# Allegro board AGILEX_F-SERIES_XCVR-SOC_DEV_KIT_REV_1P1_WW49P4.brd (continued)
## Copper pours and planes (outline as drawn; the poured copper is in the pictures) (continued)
VCCL_HPS_FPGA_0.9V on ART20: 107.29,109.6 107.29,106.17 107.27,106.16 107.27,104.28 105.32,102.33 105.32,91.19 101.68,87.54 101.68,84.66 101.69,84.65 101.69,79.84 105.69,75.84 105.69,51.03 104.34,49.68 78.84,49.68 69.42,40.26 55.2,40.26 48.26,47.19 46.15,47.19 38.51,39.55 18.87,39.55 15.53,42.89 15.53,98.87 31.47,114.81 57.68,114.81 64.54,107.95 86.11,107.95 88.34,110.19 91.8,110.19 94.11,112.5 100.51,112.5 103.15,109.85 107.03,109.85
VCCL_SDM_FPGA_0.8V on BOTTOM: 123.57,76.4 123.62,76.35 129.54,76.35 129.61,76.43 129.61,78.33 128.83,79.12 124.21,79.12 123.57,78.48
VCCL_SDM_FPGA_0.8V on BOTTOM: 129.59,27.13 129.29,27.43 129.29,29.82 129.44,29.97 131.75,29.97 131.98,29.74 131.98,27.3 131.8,27.13
VCCL_SDM_FPGA_0.8V on POWER09: 125.96,27.38 125.96,59.41 114.02,71.35 114.02,93.37 114.12,93.47 116.28,93.47 116.69,93.87 116.69,95.27 116.79,95.38 120.52,95.38 120.62,95.27 120.62,81.3 122.8,79.12 126.49,79.12 130.55,75.06 134.47,75.06 134.47,73.55 141.7,66.31 141.7,27.74 140.74,26.77 126.57,26.77
VCCLPLLDIG_HPS_FPGA_0.9V on BOTTOM: 68.17,98.17 68.17,100.84 68.43,101.09 70.33,101.09 70.58,100.84 70.58,98.42 70.33,98.17
VCCLPLLDIG_HPS_FPGA_0.9V on ART03: 104.87,112.01 105.38,111.51 105.38,109.73 93.85,98.2 68.43,98.2 68.06,98.56 68.06,107.35 69.93,109.22 95,109.22 97.79,112.01
VCCLPLLDIG_SDM_FPGA_0.8V on BOTTOM: 130.3,79.04 133.3,79.04 133.5,78.84 133.5,76.48 133.22,76.2 130.32,76.2 130.02,76.5 130.02,78.76
VCCLPLLDIG_SDM_FPGA_0.8V on POWER09: 130.76,75.56 126.7,79.63 123.01,79.63 121.13,81.51 121.13,93.49 121.15,93.47 123.9,93.47 124.05,93.62 124.05,92.1 124.71,91.44 132.84,91.44 134.47,89.81 134.47,75.56
VCCPT_FLTR_FPGA_1.8V on BOTTOM: 154.36,78.54 154.36,76.94 153.59,76.17 153.59,70.64 158.95,65.28 160.05,65.28 162.1,67.34 162.1,80.06 161.85,80.31 159.87,80.31 158.83,79.27 155.09,79.27
VCCPT_FLTR_FPGA_1.8V on ART16: 107.82,115.06 113.41,109.47 115.57,109.47 117.09,107.95 117.09,95.63 119.38,93.34 126.11,93.34 127,92.46 127,91.82 126.24,91.06 122.94,91.06 121.67,89.79 121.67,81.92 124.71,78.87 129.92,78.87 131.32,77.47 131.32,75.18 140.02,66.48 145.1,66.48 146.3,65.28 150.75,65.28 155.19,69.72 159.38,69.72 160.27,68.83 160.27,66.29 157.73,63.75 138.56,63.75 130.56,71.75 123.44,71.75 113.67,81.53 113.67,88.77 112.39,90.04 112.39,91.69 106.36,97.73 106.36,105.6 100.97,111 100.97,114.68 101.35,115.06
VCCPT_FPGA_1.8V on TOP (solid shape): outline of 209 points within 205.79,119.1 216.71,130.05
VCCPT_FPGA_1.8V on TOP (solid shape): outline of 305 points within 187.68,118.64 199.49,130.1
VCCPT_FPGA_1.8V on BOTTOM: 208.45,122.95 207.11,124.28 207.11,126.92 206.32,127.71 202.21,127.71 201.9,127.41 199.97,127.41 199.49,126.92 199.49,124.54 199.11,124.16 198.32,124.16 198.07,123.9 198.07,119.76 197.66,119.35 193.5,119.35 192.25,120.6 192.25,121.69 192.28,121.72 191.9,122.1 189.99,122.1 189.71,121.82 189.71,121.41 189.36,121.77 187.58,121.77 187.27,121.46 187.27,117.63 187.5,117.4 188.19,117.4 188.94,116.65 188.94,112.1 188.57,111.73 161.77,111.73 161.76,111.75 160.26,111.75 157.33,114.68 154.4,114.68 151.86,112.14 144.75,112.14 144.5,112.39 144.5,115.01 144.55,115.06 150.42,115.06 153.38,118.02 157.14,118.02 157.61,118.49 157.61,125.09 156.72,125.98 156.72,127.38 156.34,127.76 156.34,129.41 162.18,129.41 162.51,129.08 192.35,129.08 192.89,128.55 194.56,128.55 196.16,130.15 216.15,130.15 216.89,129.41 216.89,119.51 216.56,119.18 214.58,119.18 214.12,118.72 209.32,118.72 208.45,119.6
VCCPT_FPGA_1.8V on BOTTOM: 155.83,92.53 155.83,93.32 156.1,93.59 157.53,93.59 158.56,94.61 161.37,94.61 162.38,93.6 162.38,89.66 161.47,88.75 161.47,85.67 162.31,84.84 162.31,81.41 161.9,81 159.33,81 158.22,79.88 153.67,79.88 151.13,82.42 151.13,90.14 152.43,91.44 154.74,91.44
VCCPT_FPGA_1.8V on GND13: 215.49,142.62 215.49,116.26 215.01,115.77 193.07,115.77 191.87,116.97 191.87,140.87 194.56,143.56 214.55,143.56
VCCPT_FPGA_1.8V on POWER14: 115.54,108.71 110.24,108.71 109.73,108.2 109.73,95 110.24,94.49 115.42,94.49 115.92,95 115.92,95 116.18,95.25 118.72,95.25 119.48,94.49 122.94,94.49 123.44,93.98 123.44,79.25 124.46,78.23 158.72,78.23 159.55,79.06 159.55,94.71 158.85,95.4 158.85,102.95 159.54,103.63 187.45,103.63 200.15,116.33 200.15,121.51 200.1,121.56 200.1,122.07 200.15,122.12 200.15,145.8 199.64,146.3 182.88,146.3 182.8,146.23 154.35,146.23 153.67,145.54 153.67,138.3 152.32,136.96 128.32,136.96 119.89,128.52 119.89,109.22 118.87,108.2 118.84,108.2 118.72,108.08 116.18,108.08
VCCRT_GXE_FPGA_0.9V on BOTTOM: 81.13,89.03 81.13,102.54 80.95,102.72 80.7,102.72 80.67,102.74 79.04,102.74 76.73,105.05 74.01,105.05 71.12,107.95 70.46,107.95 69.82,108.58 69.82,112.24 70.28,112.7 90.7,112.7 92.25,111.15 92.25,89.86 91.41,89.03
VCCRT_GXE_FPGA_0.9V on POWER14: 100.11,106.11 100.18,106.04 103.6,106.04 104.24,105.41 104.24,78.61 103.86,78.23 81.51,78.23 80.49,79.25 80.49,95.45 72.42,103.53 72.42,108.53 73.86,109.98 99.67,109.98 100.11,109.54
VCCRT_GXE_FPGA_0.9V on ART16: 81.25,89.41 81.25,91.73 78.32,94.67 78.32,105.61 78.77,106.06 97.19,106.06 97.91,105.34 97.91,101.16 97.38,100.63 97.38,98.32 97.47,98.23 97.49,98.23 97.91,97.82 97.91,94.32 92.61,89.01 81.65,89.01
VCCRT_GXP_FPGA_0.9V on BOTTOM: 141.32,113.54 139.42,113.54 138.91,113.03 138.91,105.69 139.32,105.28 141.81,105.28 141.83,105.31 141.83,113.03
VCCRT_GXP_FPGA_0.9V on POWER09: 134.82,90.17 133.05,91.95 124.92,91.95 124.56,92.31 124.56,109.49 124.92,109.85 147.29,109.85 147.29,90.66 146.81,90.17
VCCRTPLL_GXE_FPGA_0.9V on BOTTOM: 77.37,94.26 75.77,94.26 75.44,93.93 75.44,85.37 75.66,85.14 77.24,85.14 77.77,85.67 77.77,93.85
VCCRTPLL_GXE_FPGA_0.9V on ART16: 77.04,82.02 75.79,83.26 75.79,91.77 76.05,92.02 80.24,92.02 81.78,90.49 84.44,90.49 85.98,92.02 89.84,92.02 97.73,99.92 97.73,100.69 98.2,101.16 98.2,102.87 98.84,103.52 103.35,103.52 104.29,102.58 104.29,92.82 103.12,91.66 102.06,91.66 98.3,87.9 98.3,82.51 97.8,82.02
VDD_SODIMM on TOP (solid shape): 80.37,50.34 80.37,49.23 80.8,48.79 80.8,48.03 80.57,47.8 80.57,42.75 79.98,42.16 78.08,42.16 77.85,42.39 77.85,47.37 79.35,48.87 79.4,48.87 79.58,49.05 79.58,49.53 79.67,49.62 79.71,49.75 79.71,50 79.63,50.18 79.45,50.26 79.21,50.26 79.14,50.28 79.07,50.28 79,50.28 78.93,50.26 78.8,50.26 78.8,50.5 80.21,50.5
VDD_SODIMM on TOP: 114,29.72 114,24.82 114.48,24.33 117.3,24.33 118.03,25.07 118.03,29.67 117.63,30.07 114.35,30.07
VDD_SODIMM on BOTTOM: 114.25,29.77 114.25,26.29 114.76,25.78 117.65,25.78 117.88,26.01 117.88,29.64 117.6,29.92 114.4,29.92
VDD_SODIMM on POWER11: 181.96,76.33 181.96,3.05 98.81,3.05 98.42,3.43 98.42,76.83 181.46,76.83
VDD_SODIMM on ART16: 67.79,57.53 118.21,57.53 124.81,50.93 124.81,42.04 123.04,40.26 68.3,40.26 67.03,41.53 67.03,56.77
(no net) on TOP: 202.46,181.64 201.93,182.17 201.93,186.44 202.18,186.69 203.86,186.69 204.32,186.23 204.32,184.35 205.54,183.13 210.74,183.13 210.78,183.17 215.79,183.17 215.81,183.2 216.4,183.2 216.41,183.19 217.17,183.19 217.37,182.98 217.37,181.89 217.12,181.64
(no net) on TOP: 200.1,208.89 194.11,208.89 193.73,208.51 193.73,206.04 194.18,205.59 200.28,205.59 200.53,205.84 200.53,208.46
(no net) on TOP: 199.21,130.1 199.49,129.82 199.49,124.54 198.36,123.41 198.36,122.59 198.88,122.07 198.88,118.77 198.75,118.64 194.89,118.64 193.19,120.35 193.19,123.14 192.38,123.95 188.39,123.95 187.68,124.66 187.68,128.17 187.91,128.4 192.86,128.4 194.56,130.1
(no net) on TOP: 202.53,193.31 202.23,193.6 202.23,195.15 201.4,195.99 197.66,195.99 197.36,196.29 197.36,197 196.8,197.56 189.66,197.56 189.26,197.97 189.26,200.08 189.87,200.69 199.21,200.69 199.67,201.14 199.67,201.52 199.86,201.71 201.74,201.71 201.88,201.57 201.88,198.37 202.29,197.97 207.24,197.97 207.52,198.25 207.52,202.95 208.38,203.81 208.38,208.56 208,208.94 208,211.51 208.13,211.63 209.65,211.63 211.18,210.11 214.93,210.11 216.69,208.36 216.69,195.53 216.48,195.33 214.99,195.33 214.35,195.96 206.48,195.96 205.89,195.38 205.89,193.6 205.6,193.31
(no net) on TOP: 203.45,192.56 203.45,190.88 203.84,190.5 206.55,190.5 206.98,190.07 206.98,188.9 207.54,188.34 209.37,188.34 209.68,188.65 209.68,190.45 209.02,191.11 208.74,191.11 208.74,191.54 207.8,192.48 207.19,192.48 206.78,192.89 203.78,192.89
(no net) on TOP: 207.19,195.35 207.19,193.32 207.57,192.94 207.9,192.94 209.07,191.77 209.35,191.77 209.8,191.31 209.8,188.26 210.16,187.91 210.16,186.03 211.66,184.53 216.15,184.53 216.6,184.98 216.6,194.32 215.99,194.93 214.88,194.93 214.26,195.55 207.39,195.55
(no net) on TOP: 202.06,127.05 202.06,125.37 202.44,124.99 205.16,124.99 205.59,124.56 205.59,123.72 205.74,123.57 207.77,123.57 207.77,123.75 208.28,124.26 208.28,125.98 207.75,126.52 206.58,126.52 205.69,127.41 205.38,127.41 205.38,127.38 202.39,127.38
(no net) on TOP: 201.13,127.8 200.84,128.09 200.84,129.64 200,130.48 194.23,130.48 193.78,130.02 186.54,130.02 186.26,130.3 186.26,132.08 186.82,132.64 193.47,132.64 193.8,132.97 193.8,134.29 194.69,135.18 197.82,135.18 198.27,135.64 198.27,136.02 198.46,136.21 200.34,136.21 200.48,136.07 200.48,132.87 200.89,132.46 205.84,132.46 206.12,132.74 206.12,140.18 207.16,141.22 207.16,148.74 207.26,148.84 211.81,148.84 211.84,148.87 216.26,148.87 217.37,147.75 217.37,131.17 216.61,130.4 213.36,130.4 212.75,131.01 211.28,131.01 210.72,130.45 205.08,130.45 204.5,129.87 204.5,128.09 204.2,127.8
(no net) on TOP: 202.06,185.9 202.11,185.95 203.76,185.95 204.11,185.6 204.11,184.28 203.84,184 202.18,184 202.06,184.12
(no net) on TOP: 85.09,50.77 79.04,50.77 78.84,50.98 78.84,51.16 78.89,51.21 79.98,51.21 80.54,51.77 80.54,53.04 81.23,53.72 88.54,53.72 89.15,53.11 89.15,52.45 90.3,51.31 91.19,51.31 91.31,51.18 91.31,48.26 87.6,48.26
(no net) on TOP: 200.9,133.16 201.12,132.94 205.51,132.94 205.71,133.15 205.71,137.67 205.51,137.87 205.51,148.69 205.26,148.95 201.29,148.95 200.66,148.31 200.66,142.39 200.48,142.21 200.48,140.31 200.56,140.23 200.84,140.23 201.09,139.98 201.09,138.66 201.93,137.82 201.93,136.5 201.65,136.22 201.23,136.22 200.9,135.89
(no net) on TOP: 84.86,50.37 86.33,48.9 86.33,45.47 86.09,45.22 84.07,45.22 83.81,44.96 83.82,44.96 83.82,42.67 83.31,42.16 81.15,42.16 80.98,42.34 80.98,47.29 81.23,47.55 81.23,49.05 80.87,49.4 80.87,50.16 81.08,50.37
(no net) on TOP: 57.18,131.85 57.18,129.95 57.06,129.83 55.11,129.83 54.95,129.98 53.1,129.98 52.73,130.35 52.73,131.95 53.1,132.32 55.13,132.32 55.45,132 57.02,132
(no net) on TOP: 205.79,129.84 205.79,127.76 206.45,127.1 206.88,127.1 207.26,126.72 207.26,126.7 208.05,126.7 208.41,126.34 208.41,122.76 208.76,122.4 209.83,122.4 210.77,121.46 210.77,119.94 211.61,119.1 216.46,119.1 216.71,119.35 216.71,128.3 216.2,128.8 213.31,128.8 212.06,130.05 205.99,130.05
(no net) on TOP: 202.3,198.67 202.51,198.45 206.91,198.45 207.11,198.65 207.11,203.17 206.68,203.61 206.68,212.45 206.32,212.8 204.47,212.8 203.28,214 201.68,214 201.19,213.51 201.19,205.84 201.45,205.59 202.49,205.59 202.77,205.31 202.77,203.45 203.25,202.97 203.25,202.3 203.03,202.08 202.64,202.08 202.3,201.74
(no net) on TOP: 79.98,42.16 80.57,42.75 80.57,47.8 80.8,48.03 80.8,48.79 80.37,49.23 80.37,50.34 80.2,50.51 79.62,50.51 79.58,50.55 78.71,50.55 78.66,50.5 78.66,50.29 78.71,50.24 79.3,50.24 79.58,49.96 79.58,49.05 79.4,48.87 79.35,48.87 77.85,47.37 77.85,42.39 78.08,42.16
(no net) on TOP: 199.85,140.39 199.85,145.41 199.26,146 194.56,146 194.26,145.69 194.26,140.87 194.89,140.23 199.69,140.23
(no net) on TOP: 200.61,195.61 200.89,195.33 200.89,190.04 199.76,188.91 199.76,188.1 200.28,187.58 200.28,184.28 200.05,184.05 194.77,184.05 193.78,185.04 193.78,190.98 193.6,191.16 189.59,191.16 188.82,191.92 188.82,196.52 189.15,196.85 196.67,196.85 196.98,196.55 196.98,196.14 197.51,195.61
(no net) on BOTTOM: 4.79,181.34 5.36,181.91 8.98,181.91 9.49,181.4 9.49,177.97 7.84,176.32 7.84,170.99 8.86,169.97 11.52,169.97 12.22,169.27 12.22,162.23 11.91,161.92 5.18,161.92 4.79,162.31
(no net) on BOTTOM: 217.42,207.82 217.6,207.82 217.91,207.52 217.91,198.98 217.86,198.98 217.2,198.32 213.44,198.32 212.24,197.13 212.24,196.19 211.98,195.92 207.48,195.92 207.21,195.66 207.21,193.4 206.91,193.09 206.04,193.09 205.97,193.01 202.59,193.01 202.31,193.29 202.31,194.84 201.12,196.04 197.33,196.04 195.86,197.51 188.8,197.51 188.37,197.94 188.37,203.1 192.99,207.72 192.99,214.66 194.21,215.87 199.97,215.87 200.74,215.11 200.74,204.95 199.54,203.76 199.54,201.98 199.92,201.6 201.78,201.6 201.83,201.55 201.83,198.42 202.49,197.76 206.83,197.76 207.52,198.45 207.52,202.67 208.41,203.56 208.41,208.71 209.17,209.47 216.46,209.47 217.42,208.51
(no net) on BOTTOM: 198.35,136.83 198.68,136.5 200.41,136.5 200.91,135.99 200.91,133.15 201.14,132.92 205.51,132.92 205.97,133.38 205.97,148.26 205.44,148.79 201.47,148.79 201.27,148.59 201.27,139.85 200.43,139.01 199.06,139.01 198.35,138.3
(no net) on BOTTOM: 200.74,205.54 200.23,205.03 198.55,205.03 197.87,205.71 197.87,210.41 196.85,211.43 194.64,211.43 193.68,212.39 193.68,215.21 194.26,215.8 200.03,215.8 200.74,215.09
(no net) on BOTTOM: 13.33,169.84 12.75,169.27 12.75,166.14 12.79,166.1 12.79,162.44 13.18,162.05 15.85,162.05 16.36,162.56 16.36,169.27 15.78,169.84
(no net) on BOTTOM: 194.11,139.83 193.73,140.21 193.73,152.07 194.18,152.53 199.21,152.53 199.54,152.2 199.54,140.16 199.21,139.83
(no net) on BOTTOM: 202.35,203.82 201.93,203.4 200.18,203.4 199.75,202.97 199.75,202.21 199.92,202.03 201.75,202.03 202.16,201.63 202.16,198.58 202.41,198.32 207.09,198.32 207.26,198.5 207.26,203.2 207.37,203.3 207.37,212.27 207.06,212.57 205.59,212.57 204.04,214.12 202.31,214.12 202.18,214 202.18,212.22 202.35,212.05
(no net) on BOTTOM: 193.57,186.13 192.74,186.97 192.74,190.17 192.2,190.7 188.87,190.7 188.26,191.31 188.26,196.52 188.65,196.9 195.43,196.9 196.65,195.68 200.38,195.68 200.89,195.17 200.89,187.02 200,186.13
(no net) on BOTTOM: 216.71,194.31 216.81,194.21 216.81,185.14 216.38,184.71 211.76,184.71 211.46,185.01 211.46,186.84 208.51,189.79 208.51,193.73 207.62,194.61 207.62,195.28 207.98,195.63 211.89,195.63 213.21,194.31
(no net) on BOTTOM: 29.49,21.44 31.65,19.28 31.65,10.47 30.82,9.64 28.56,9.64 28.47,9.55 25.4,9.55 25.37,9.58 25.07,9.58 24.49,8.99 24.49,8 24.05,7.57 18.49,7.57 18.16,7.9 18.16,20.8 18.8,21.44 ; 1 cut-out
(no net) on BOTTOM: 207.62,181.64 217.32,181.64 217.42,181.74 217.42,182.98 217.32,183.08 216.48,183.08 216.38,182.98 209.19,182.98 208.98,183.2 205.8,183.2 205.51,183.49 200,183.49 199.67,183.82 199.67,184.68 199.36,184.99 197.03,184.99 196.67,184.63 196.67,182.35 196.93,182.09 202.9,182.09 203.02,182.22 207.04,182.22
(no net) on BOTTOM: 216.51,131.17 216,130.66 195.66,130.66 195.53,130.78 191.41,130.78 191.11,131.09 191.11,134.29 192.18,135.36 195.5,135.36 196.44,136.3 200.23,136.3 200.71,135.81 200.71,133.15 201.04,132.82 205.59,132.82 206.04,133.27 206.04,137.44 207.06,138.46 207.06,140.31 206.27,141.1 206.27,148.23 206.83,148.79 214.22,148.79 216.51,146.51
(no net) on ART03: 15.88,8.89 16.18,9.19 23.77,9.19 25.43,7.54 32.72,7.54 32.73,7.53 39.84,7.53 40.18,7.19 40.18,4.98 39.93,4.72 32.97,4.72 32.94,4.75 16.3,4.75 15.88,5.18
(no net) on ART05: 204.22,114.38 208.89,114.38 209.6,115.09 209.6,126.87 208.51,127.97 202.72,127.97 202.16,127.41 202.16,122.33 202.82,121.67 204.04,121.67 205.18,120.52 205.18,119.28 204.83,118.92 203.71,118.92 203.38,118.59 203.38,115.21
(no net) on ART05: 211,182.37 211,192.38 209.91,193.47 204.11,193.47 203.56,192.91 203.56,187.83 204.22,187.17 205.44,187.17 206.58,186.03 206.58,184.78 206.22,184.43 205.1,184.43 204.77,184.1 204.77,182.27 205.18,181.86 210.49,181.86
(no net) on ART07: 22.48,20.57 23.88,21.97 35.86,21.97 38.73,19.1 41.15,19.1 42.52,17.73 42.52,14.61 43.15,13.97 43.15,10.39 41.91,9.14 22.96,9.14 22.48,9.62
CLEANER_VDDO1 on BOTTOM: 177.47,56.72 177.98,56.72 178.77,55.93 178.77,55.19 178.61,55.04 178.33,55.04 177.11,56.26 177.11,56.36
LTM4677_VDD33 on BOTTOM: 184.68,163.53 186.89,163.53 187.07,163.7 187.07,168.53 186.97,168.63 184.78,168.63 184.56,168.4 184.56,163.65
LTM4678_1_VDD33 on ART07: 200.56,183.34 201.47,183.34 202.01,183.87 204.27,183.87 204.93,183.21 215.54,183.21 216.48,184.15 216.48,193.52 216.45,193.56 216.45,200.83 215.93,201.35 196.77,201.35 196.09,200.66 196.09,199.95 196.8,199.24 211.94,199.24 212.17,199.01 212.17,195.1 211.46,194.39 206.4,194.39 206.04,194.03 206.04,193.07 206.27,192.84 206.93,192.84 207.21,192.56 207.21,192.23 207.59,191.85 213.44,191.85 213.61,191.67 213.61,188.19 212.6,187.17 200.58,187.17 199.82,186.41 199.82,184.07
LTM4678_2_VDD33 on ART07: 197.82,121.44 197.82,120.5 199.77,118.54 199.77,117.7 200.71,116.76 214.12,116.76 216.89,119.53 216.89,127.97 215.72,129.13 204.77,129.13 204.52,128.88 204.52,126.31 204.83,126.01 211.79,126.01 212.14,125.65 212.14,122.73 211.15,121.74 198.12,121.74
QSFPDD_VCC on TOP: 53.19,70.76 57.86,70.76 58.6,71.5 59.41,71.5 59.43,71.47 64.72,71.47 65.46,72.21 70.61,72.21 70.92,71.91 70.92,70.61 70.64,70.33 59.13,70.33 58.9,70.1 53.19,70.1 53.06,70.23 53.06,70.64
QSFPDD_VCCRX on TOP: 46.84,70.08 45.41,70.08 45.22,69.89 45.22,69.73 45.18,69.7 45.18,68.83 45.64,68.38 46.76,68.38 47.19,68.81 51.86,68.81 52.07,69.01 52.07,69.39 51.86,69.6 47.32,69.6
QSFPDD_VCCRX on BOTTOM: 46.45,70.59 40.46,70.59 39.85,69.98 39.85,67.59 40.28,67.16 45.03,67.16 45.13,67.26 45.13,68.05 45.49,68.4 50.01,68.4 50.39,68.78 50.39,69.29 50.09,69.6 47.44,69.6
QSFPDD_VCCTX on TOP: 53.26,69.98 61.14,69.98 61.34,70.18 70.38,70.18 70.74,69.82 70.74,68.81 70.56,68.63 66.85,68.63 66.76,68.54 65.37,68.54 64.72,69.19 53.29,69.19 53.06,69.42 53.06,69.77
SODIMM_VDDQ_AGND on BOTTOM: 110.52,18.11 110.31,17.91 110.31,14.48 109.58,13.74 108.25,13.74 107.62,13.11 107.62,12.9 107.65,12.88 107.65,12.04 107.47,11.86 106.63,11.86 106.45,12.04 106.45,14.2 106.76,14.5 108.23,14.5 108.81,15.09 108.81,19.13 109.12,19.43 113.61,19.43 113.89,19.71 113.89,22.91 113.82,22.99 112.98,22.99 112.9,23.06 112.9,23.98 113.72,24.79 114.55,24.79 114.83,25.07 120.35,25.07 120.7,24.71 120.7,22.56 120.57,22.43 119.79,22.43 119.61,22.61 119.61,24.03 119.23,24.41 115.44,24.41 114.73,23.7 114.73,20.75 114.91,20.57 115.29,20.57 115.57,20.29 115.57,18.39 115.77,18.19 116.1,18.19 116.28,18.01 116.28,17.35 116.18,17.25 115.09,17.25 114.8,17.54 114.8,13.17 115.14,12.83 116.92,12.83 117.2,13.11 117.2,14.38 117.27,14.45 117.96,14.45 117.96,13.97 118.03,13.89 118.06,13.89 118.26,13.69 118.26,12.37 117.83,11.94 114.43,11.94 113.97,12.4 113.97,17.83 113.69,18.11
VREF_DDR4_COMP_0.6V on ART07: 125.91,150.72 128.55,150.72 128.55,150.72 129.31,150.72 129.79,150.24 129.79,148.87 129.26,148.34 128.14,148.34 127.33,149.15 126.72,149.15 125.73,150.14 125.73,150.54
VREF_DDR4_COMP_0.6V on ART16: 126.31,155.07 127.66,155.07 127.89,154.84 127.89,150.47 127.53,150.11 125.68,150.11 125.35,150.44 125.35,154.91 125.52,155.09 126.29,155.09
VREF_FPGA_0.6V on BOTTOM: 94.97,75.44 93.19,75.44 92.94,75.69 92.94,77.6 93.19,77.85 94.84,77.85 95.1,77.6 95.1,75.56
VREF_FPGA_0.6V on ART07: 102.84,87.5 101.32,85.98 101.32,82.68 101.38,82.61 101.38,79.69 95.86,74.17 93.65,74.17 93.65,74.19 93.16,74.68 93.16,76.99 94.03,77.85 95.88,77.85 97.66,79.63 97.66,87.02 104.75,94.11 113.38,94.11 116.69,97.41 116.81,97.41 116.81,108.2 115.67,109.35 105.89,109.35 104.87,110.36 104.87,112.01 105.89,113.03 117.57,113.03 119.73,110.87 119.73,90.42 116.81,87.5
VTT_DDR4_COMP_0.6V on TOP: 140.87,152.27 140.84,152.27 140.08,153.03 140.08,157.48 137.31,160.25 119.45,160.25 119.12,159.92 119.12,158.09 119.5,157.71 120.9,157.71 120.93,157.73 129.05,157.73 129.39,157.4 129.39,145.31 130.02,144.68 130.02,140.26 130.27,140 135.94,140 136.78,140.84 136.78,144.93 137.74,145.9 140.92,145.9 141.35,145.47 141.35,144.58 141.38,144.55 141.58,144.55 141.6,144.58 141.6,145.92 142.09,146.41 142.09,151.59 141.76,151.92 141.22,151.92
VTT_DDR4_COMP_0.6V on BOTTOM: 141.86,144.27 142.49,144.91 142.49,151.75 141.99,152.26 141.97,152.26 140.61,153.62 138.71,153.62 137.92,154.41 137.92,158.52 136.65,159.79 129.92,159.79 129.39,159.26 129.39,145.67 129.41,145.64 129.41,142.39 129.41,142.39 129.41,139.73 129.69,139.45 135.71,139.45 136.09,139.83 136.09,143.89 136.47,144.27
VTT_SODIMM_0.6V on TOP (solid shape): outline of 99 points within 79.65,48.26 91.31,53.72
VTT_SODIMM_0.6V on BOTTOM: 89.86,51.18 90.78,51.18 91.03,50.93 91.03,48.26 86.84,48.26 86.33,48.77 86.33,51.33 86.64,51.64 89.41,51.64
VTT_SODIMM_0.6V on BOTTOM: 82.35,50.7 84.89,50.7 85.34,51.16 85.34,54.23 85.09,54.48 82.6,54.48 82.12,54 82.12,50.93
ZQSFP_VCC on TOP: 50.29,98.4 58.65,98.4 58.87,98.18 58.87,97.32 58.67,97.13 51.13,97.13 50.59,96.6 50.59,95.45 49.58,94.44 45.74,94.44 45.59,94.59 45.59,95.02 45.69,95.12 48.23,95.12 49.63,96.52 49.63,97.74
ZQSFP_VCCR on TOP: 43.05,93.93 44.75,93.93 44.93,93.75 44.93,93.34 44.73,93.14 41.68,93.14 41.48,93.34 41.48,94.03 41.6,94.16 42.82,94.16
ZQSFP_VCCR on BOTTOM: 34.26,93.22 44.96,93.22 45.44,93.7 45.44,95.88 45.06,96.27 34.39,96.27 34,95.87 34,94.98 34.01,94.97 34.01,93.47
ZQSFP_VCCT on TOP: 51.05,94.77 58.83,94.77 59.21,94.39 59.21,93.29 58.75,92.84 51.38,92.84 50.77,93.45 45.82,93.45 45.57,93.7 45.57,94.06 45.67,94.16 50.44,94.16
N17498664 on BOTTOM: 20.01,47.55 20.01,48.14 19.89,48.26 15.72,48.26 15.59,48.14 15.59,47.58 15.8,47.37 19.84,47.37
N17498798 on BOTTOM: 21.82,47.86 21.03,47.86 20.42,47.24 20.17,47.24 20.12,47.25 19.94,47.07 18.06,47.07 17.86,46.86 17.86,46.13 20.32,46.13 20.75,46.56 21.59,46.56 21.82,46.79
N17579540 on BOTTOM: 88.26,33.07 87.73,33.07 87.58,32.92 87.58,31.01 87.75,30.83 89.66,30.83 89.89,30.61 89.89,30.25 90.24,29.89 91.59,29.89 91.77,30.07 91.77,31.83 91.49,32.1 88.75,32.1 88.44,32.41 88.44,32.89
N17579564 on BOTTOM: 89,39.32 89.99,39.32 90.42,39.75 92.05,39.75 92.17,39.62 92.17,38.48 92,38.3 89.02,38.3 88.41,37.69 88.41,37.06 88.31,36.96 88.11,36.96 88.01,37.06 88.01,37.9 88.11,38 88.11,38.43
N17579748 on BOTTOM: 98.78,35.05 97.38,35.05 97.38,41.4 98.4,41.4 98.78,41.02
N18128423 on TOP: 170.03,137.29 170.03,136.91 169.14,136.91 169.01,136.78 168.88,136.91 168.88,137.54 171.55,140.21 172.95,140.21 172.95,138.68 171.42,138.68
N18991424 on BOTTOM: 42.01,48.21 41.45,48.21 41.32,48.08 41.32,45.01 41.5,44.83 41.88,44.83 41.97,44.92 42.01,44.92
N19408803 on TOP (solid shape): 36.04,201.4 33.93,201.4 33.93,201.78 34.36,201.78 34.36,202.06 33.93,202.06 33.93,202.44 34.36,202.44 34.36,202.69 33.93,202.69 33.93,203.07 34.36,203.07 34.36,203.35 33.93,203.35 33.93,203.73 36.04,203.73
N19408803 on TOP, BOTTOM, ART03, ART05, ART07, ART16, ART18, ART20: 36.17,194.94 30.07,194.94 30.07,212.72 36.17,212.72
N20605183 on TOP: 172.95,138.05 171.8,138.05 171.8,137.41 170.91,136.52 170.15,136.52 169.64,136.02 169.14,136.02 168.88,135.76 169.64,135 170.15,135 170.15,135.51 170.41,135.76 172.31,135.76 172.95,136.4
N24167599 on BOTTOM: 42.26,48.11 42.26,44.5 42.8,43.97 43.69,43.97 43.79,44.07 43.79,48.11 43.66,48.23 42.39,48.23
N24972013 on TOP (solid shape): 204.47,212.8 206.32,212.8 206.68,212.45 206.68,203.61 207.11,203.17 207.11,198.65 206.91,198.45 202.51,198.45 202.3,198.67 202.3,201.74 202.64,202.08 203.03,202.08 203.25,202.3 203.25,202.42 203.26,202.44 203.31,202.56 203.33,202.69 203.27,202.92 203.12,203.1 202.77,203.45 202.77,205.31 202.49,205.59 201.45,205.59 201.19,205.84 201.19,213.51 201.68,214 203.28,214
N24972013 on BOTTOM (solid shape): 204.01,214.12 204.48,213.34 205.27,212.89 205.59,212.57 207.06,212.57 207.37,212.27 207.37,203.3 207.26,203.2 207.26,198.5 207.09,198.32 202.41,198.32 202.16,198.58 202.16,201.63 201.75,202.03 199.92,202.03 199.75,202.21 199.75,202.97 200.18,203.4 201.93,203.4 202.35,203.82 202.35,212.05 202.18,212.22 202.18,214 202.31,214.12
N24979885 on TOP (solid shape): 205.51,148.69 205.51,137.87 205.71,137.67 205.71,133.15 205.51,132.94 201.12,132.94 200.9,133.16 200.9,135.89 201.23,136.22 201.65,136.22 201.93,136.5 201.93,137.17 201.93,137.82 201.09,138.66 201.09,139.98 200.84,140.23 200.56,140.23 200.48,140.31 200.48,142.21 200.66,142.39 200.66,148.31 201.29,148.95 205.26,148.95
N24979885 on BOTTOM (solid shape): 205.97,148.26 205.97,133.38 205.51,132.92 201.14,132.92 200.91,133.15 200.91,135.99 200.41,136.5 198.68,136.5 198.35,136.83 198.35,138.3 199.06,139.01 200.43,139.01 201.27,139.85 201.27,148.59 201.47,148.79 205.44,148.79
N24984332 on TOP: 76.61,51.74 75.97,51.74 75.87,51.84 75.87,52.86 75.9,52.88 75.9,54.41 76,54.51 76.45,54.51 76.63,54.33 76.63,51.77
N24984340 on TOP: 78.66,51.77 79.38,51.77 79.45,51.84 79.45,53.39 79.35,53.49 78.82,53.49 78.66,53.34
N24985204 on TOP: 139.83,140.36 138.96,140.36 138.86,140.46 138.86,142.11 139.22,142.47 140.59,142.47 140.61,142.44 140.61,141.68 140,141.07 140,140.54
N25067542 on TOP: 23.34,31.89 22.85,31.89 22.45,32.28 22.45,36.65 22.25,36.86 19.02,36.86 18.75,36.58 18.75,25.3 19.04,25.01 22.21,25.01 22.58,25.37 22.58,29.57 23.63,30.62 23.63,31.6
N25067542 on BOTTOM: 21.97,24.97 18.92,24.97 18.49,25.4 18.49,29.69 19.13,30.33 19.13,36.75 18.59,37.29 17.53,37.29 17.27,37.54 17.27,39.29 17.54,39.56 21.07,39.56 22.12,38.51 22.73,38.51 23.04,38.2 23.04,36.22 23.85,35.41 23.85,32.28 23.62,32.05 23.62,30.71 23.52,30.61 22.83,30.61 22.3,30.07 22.3,25.3
N25077282 on TOP: 134.34,27.46 123.14,27.46 122.72,27.04 122.72,23.66 123.24,23.14 126.11,23.14 127.17,22.09 131.97,22.09 132.18,22.3 132.18,22.89 132.44,23.14 134.57,23.14 134.98,23.55 134.98,26.82
N25077282 on BOTTOM: 122.86,27.33 123.19,27.66 126.85,27.66 127.23,27.28 127.23,26.29 127.46,26.06 129.24,26.06 129.9,26.72 132.54,26.72 133.15,26.11 134.62,26.11 135.15,25.58 135.15,22.3 134.71,21.86 128.46,21.86 127.76,22.56 123.44,22.56 122.86,23.14
N25080791 on TOP: 5.94,34.94 5.45,34.94 5.05,35.33 5.05,39.83 4.9,39.98 1.6,39.98 1.35,39.73 1.35,28.65 1.65,28.35 4.85,28.35 5.18,28.68 5.18,31.75 6.24,32.8 6.24,34.65
N25080791 on BOTTOM: 4.57,28.02 1.52,28.02 1.09,28.45 1.09,43.87 1.19,43.97 4.01,43.97 4.09,43.89 4.09,42.9 4.39,42.6 4.98,42.6 5.49,42.09 5.49,40.51 5.74,40.26 5.92,40.26 6.3,39.88 6.3,35.08 6.27,35.05 6.27,33.78 6.15,33.66 5.44,33.66 4.9,33.12 4.9,28.35
N25084297 on TOP: 25.04,153.95 25.04,148.13 25.17,148.01 25.17,145.01 25.4,144.78 26.72,144.78 26.9,144.6 26.9,142.42 26.44,141.96 25.58,141.96 25.1,141.48 25.1,137.62 25.91,136.8 34.11,136.8 34.37,137.06 34.37,138.73 34.26,138.84 30.73,138.84 30.35,139.22 30.35,143.61 30.12,143.84 30.12,147.57 28.37,149.33 28.37,153.87 28.04,154.2 25.3,154.2
N25084297 on BOTTOM: 25.4,154.03 25.4,150.32 25.23,150.15 25.23,144.59 25.45,144.37 26.26,144.37 26.59,144.04 26.59,142.11 26.87,141.83 28.57,141.83 28.88,142.14 28.88,153.92 28.57,154.23 25.6,154.23
N25087810 on TOP: 40.61,34.05 40.12,34.05 39.73,34.44 39.73,38.84 39.37,39.19 36.45,39.19 36.02,38.76 36.02,27.46 36.31,27.17 39.64,27.17 39.85,27.38 39.85,31.72 40.91,32.78 40.91,33.76
N25087810 on BOTTOM: 35.76,27.86 35.76,31.85 36.11,32.19 36.11,36.06 35.93,36.23 35.93,37.91 35.08,38.76 35.08,40.77 35.18,40.87 39.75,40.87 40.26,40.36 40.26,38.81 41.33,37.74 41.33,34.49 40.97,34.14 40.97,32.87 40.87,32.77 40.13,32.77 39.09,31.72 39.09,27.66 38.84,27.41 36.22,27.41
N25093474 on TOP: 109.63,27.81 98.4,27.81 97.98,27.39 97.98,23.69 98.53,23.14 101.7,23.14 102.76,22.09 107.28,22.09 107.54,22.35 107.54,23.19 107.65,23.29 109.88,23.29 110.11,23.52 110.11,27.33
N25093474 on BOTTOM: 98.12,23.95 98.12,28.42 99.11,29.41 111.25,29.41 111.68,28.98 111.68,22.4 111.18,21.89 103.9,21.89 103.52,22.28 103.52,23.13 103.23,23.42 98.65,23.42
N25201801 on TOP: 145.47,184.38 145.47,191.87 145.87,192.28 166.01,192.28 166.93,191.36 166.93,183.03 166.73,182.83 165.33,182.83 165.05,183.11 165.05,188.85 164.03,189.87 159.21,189.87 158.75,189.41 158.75,184.76 158.39,184.4 154.51,184.4 154.05,184.86 154.05,186.69 153.77,186.97 152.1,186.97 151.43,187.63 151.43,189.43 151,189.87 148.82,189.87 147.8,188.85 147.8,184.35 147.52,184.07 145.77,184.07
N25201801 on BOTTOM: 145.49,192.15 145.49,186.92 145.75,186.66 147.42,186.66 147.83,187.07 147.83,187.6 148.36,188.14 151.36,188.14 151.46,188.24 153.52,188.24 153.53,188.25 153.92,187.86 153.92,184.96 154.28,184.61 158.55,184.61 158.78,184.84 158.78,189.33 159.33,189.89 163.32,189.89 164.95,188.26 164.95,182.7 165.3,182.35 166.75,182.35 167.18,182.78 167.18,191.69 166.5,192.38 145.72,192.38
N25850730 on TOP (solid shape): 85.99,193.21 85.74,193.21 85.74,193.62 85.49,193.62 85.49,193.21 85.24,193.21 85.24,193.62 84.99,193.62 84.99,193.21 84.74,193.21 84.74,193.62 84.49,193.62 84.49,193.21 84.24,193.21 84.24,193.62 83.99,193.62 83.99,193.21 83.74,193.21 83.74,193.62 83.49,193.62 83.49,193.21 83.24,193.21 83.24,193.62 83.02,193.62 83.02,193.83 82.61,193.83 82.61,194.09 83.02,194.09 83.02,194.56 85.99,194.56
N25850730 on TOP (solid shape): 90.71,194.09 91.12,194.09 91.12,193.83 90.71,193.83 90.71,193.62 90.5,193.62 90.5,193.21 90.24,193.21 90.24,193.62 90,193.62 90,193.21 89.74,193.21 89.74,193.62 89.5,193.62 89.5,193.21 89.24,193.21 89.24,193.62 89,193.62 89,193.21 88.74,193.21 88.74,193.62 88.5,193.62 88.5,193.21 88.24,193.21 88.24,193.62 88,193.62 88,193.21 87.74,193.21 87.74,194.56 90.71,194.56
N25850730 on TOP: 84.33,187.71 84.32,187.72 83.65,187.72 82.6,188.77 82.6,194.13 83.03,194.56 85.95,194.56 85.98,194.54 85.98,192.94 86.18,192.74 87.6,192.74 87.76,192.89 87.76,194.41 87.91,194.56 90.65,194.56 91.14,194.08 91.14,188.44 90.4,187.71
N25858612 on TOP (solid shape): 100.09,192.7 99.84,192.7 99.84,193.11 99.59,193.11 99.59,192.7 99.34,192.7 99.34,193.11 99.09,193.11 99.09,192.7 98.84,192.7 98.84,193.11 98.59,193.11 98.59,192.7 98.34,192.7 98.34,193.11 98.09,193.11 98.09,192.7 97.84,192.7 97.84,193.11 97.59,193.11 97.59,192.7 97.34,192.7 97.34,193.11 97.12,193.11 97.12,193.32 96.71,193.32 96.71,193.58 97.12,193.58 97.12,194.05 100.09,194.05
N25858612 on TOP (solid shape): 104.81,193.58 105.22,193.58 105.22,193.32 104.81,193.32 104.81,193.11 104.59,193.11 104.59,192.7 104.34,192.7 104.34,193.11 104.09,193.11 104.09,192.7 103.84,192.7 103.84,193.11 103.59,193.11 103.59,192.7 103.34,192.7 103.34,193.11 103.09,193.11 103.09,192.7 102.84,192.7 102.84,193.11 102.59,193.11 102.59,192.7 102.34,192.7 102.34,193.11 102.09,193.11 102.09,192.7 101.84,192.7 101.84,194.05 104.81,194.05
N25858612 on TOP: 98.42,187.2 98.41,187.21 97.75,187.21 96.7,188.26 96.7,193.62 97.13,194.06 100.05,194.06 100.08,194.03 100.08,192.43 100.28,192.23 101.7,192.23 101.85,192.38 101.85,193.9 102.01,194.06 104.75,194.06 105.23,193.57 105.23,187.93 104.5,187.2
N25870339 on TOP (solid shape): 113.88,192.6 113.63,192.6 113.63,193.01 113.38,193.01 113.38,192.6 113.13,192.6 113.13,193.01 112.88,193.01 112.88,192.6 112.63,192.6 112.63,193.01 112.38,193.01 112.38,192.6 112.13,192.6 112.13,193.01 111.88,193.01 111.88,192.6 111.63,192.6 111.63,193.01 111.38,193.01 111.38,192.6 111.13,192.6 111.13,193.01 110.91,193.01 110.91,193.22 110.5,193.22 110.5,193.48 110.91,193.48 110.91,193.95 113.88,193.95
N25870339 on TOP (solid shape): 118.6,193.48 119.01,193.48 119.01,193.22 118.6,193.22 118.6,193.01 118.39,193.01 118.39,192.6 118.13,192.6 118.13,193.01 117.89,193.01 117.89,192.6 117.63,192.6 117.63,193.01 117.39,193.01 117.39,192.6 117.13,192.6 117.13,193.01 116.89,193.01 116.89,192.6 116.63,192.6 116.63,193.01 116.39,193.01 116.39,192.6 116.13,192.6 116.13,193.01 115.88,193.01 115.88,192.6 115.63,192.6 115.63,193.95 118.6,193.95
N25870339 on TOP: 112.22,187.1 112.2,187.11 111.54,187.11 110.49,188.16 110.49,193.52 110.92,193.95 113.84,193.95 113.87,193.93 113.87,192.33 114.07,192.13 115.49,192.13 115.65,192.28 115.65,193.8 115.8,193.95 118.54,193.95 119.02,193.47 119.02,187.83 118.29,187.1
N25872874 on TOP (solid shape): 126.99,192.11 126.74,192.11 126.74,192.52 126.49,192.52 126.49,192.11 126.24,192.11 126.24,192.52 125.99,192.52 125.99,192.11 125.74,192.11 125.74,192.52 125.49,192.52 125.49,192.11 125.23,192.11 125.23,192.52 124.99,192.52 124.99,192.11 124.73,192.11 124.73,192.52 124.49,192.52 124.49,192.11 124.23,192.11 124.23,192.52 124.02,192.52 124.02,192.74 123.61,192.74 123.61,192.99 124.02,192.99 124.02,193.46 126.99,193.46
N25872874 on TOP (solid shape): 131.71,192.99 132.12,192.99 132.12,192.74 131.71,192.74 131.71,192.52 131.49,192.52 131.49,192.11 131.24,192.11 131.24,192.52 130.99,192.52 130.99,192.11 130.74,192.11 130.74,192.52 130.49,192.52 130.49,192.11 130.24,192.11 130.24,192.52 129.99,192.52 129.99,192.11 129.74,192.11 129.74,192.52 129.49,192.52 129.49,192.11 129.24,192.11 129.24,192.52 128.99,192.52 128.99,192.11 128.74,192.11 128.74,193.46 131.71,193.46
N25872874 on TOP: 125.32,186.61 125.31,186.63 124.65,186.63 123.6,187.68 123.6,193.04 124.03,193.47 126.95,193.47 126.97,193.45 126.97,191.85 127.18,191.64 128.6,191.64 128.75,191.8 128.75,193.32 128.91,193.47 131.65,193.47 132.13,192.99 132.13,187.35 131.39,186.61
N25909303 on TOP: 57.45,139.42 57.45,138.71 56.92,138.18 56.18,138.18 55.98,137.97 55.98,133.6 57.76,131.83 57.76,130 57.84,129.92 59.66,129.92 60.25,130.51 60.25,139.27 60.02,139.5 57.53,139.5
N25913434 on TOP: 51.69,50.6 49.56,50.6 49.35,50.39 49.35,49.28 49.53,49.1 51.49,49.1 51.79,49.4 55.45,49.4 57.15,51.1 59.23,51.1 59.99,51.87 60.02,51.87 60.4,52.25 60.4,53.01 60.12,53.29 55.78,53.29 55.27,52.78 54.76,52.78 54.13,52.15 53.24,52.15

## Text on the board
Ref Des/Assembly Bottom: U24 | U25 | ASSEMBLY BOTTOM
Ref Des/Silkscreen Bottom: S/N | P/N | M78433-001
User.Comments: CR_ET6160LI_2 | CR_ET6160LI_3 | CR_ET6160LI_4 | CR_EM2130_1 | CR_PWE-3_1 | CR_0216_4 | CR_0216_2 | CR_1_2 | CR_0216_3 | CR_U63_1 | CR_1_4 | CR_0216_1 | CR_3_1 | CR_EM2130_2 | CR_1_1 | CR_TPS51200_2 | CR_777_4 | CR_777_2 | CR_777_3 | 01-12-22 | M78433-001 | UNLESS OTHERWISE SPECIFIED: | 1. DIMENSIONS ARE IN INCHES | 2. BREAK ALL SHARP EDGES | 3. DO NOT SCALE DRAWING | 4. TOLERANCES | ANGLES +/- | xxx +/- | xx +/- | .01 | .005 | 2 DEGREES | CHK BY | APVD | DRN BY | ENGR | SIGNATURE | VS | JS | PG | AK | DATE | SIZE | SCALE | TITLE | D | C | DCLC | 1/1 | AGILEX_F-SERIES_XCVR-SOC_DEV_KIT | CLASS CODE | REV_1P1_WW49P4 | 3065 BOWERS AVE | DOCUMENT NUMBER | CALIF.  95051 | SANTA CLARA | SHEET | 1 | OF | REV
Ref Des/Assembly Top: ASSEMBLY TOP
Ref Des/Silkscreen Top: VCCL_HPS_FPGA_0.9V | MXP_RXN3 | MXP_RXP3 | JTAG_TX | JTAG_RX | SC_RX | SC_TX | PWRMAX_LED_R0 | PWRMAX_LED_R1 | PWRMAX_LED_G0 | PWRMAX_LED_G1 | FPGA_LED_G7 | FPGA_LED_G6 | FPGA_LED_G5 | FPGA_LED_G4 | FPGA_LED_G3 | FPGA_LED_G2 | FPGA_LED_G1 | FPGA_LED_G0 | 3.3V | VCCIO_FPGA_1.8V | VCCCLK_GXE_FPGA_2.5V | 3.3V_PRE | VDD_SODIMM | VCCL_SDM_FPGA_0.8V | 1.8V | 12V_IN | 5V | VCCPT_FPGA_1.8V | VCCFUSEWR_SDM_FPGA_2.4V | VTT_SODIMM_0.6V | FPGA_JTAG_BYPASSn | SYSMAX_JTAG_BYPASSn | FMC_JTAG_BYPASSn | RESERVED_JTAG_BYPASSn | PCIE_JTAG_BYPASSn | MSTR0 | MSTR1 | MSTR2 | VCCIO_FPGA_1.2V | VCCH_GXE_FPGA_1.1V | UV_12V_DCIN | 1.2V | SI53311_OUTCLK_N | SMA_REFCLK_P | GXE_REFCLK_N | SI53311_OUTCLK_P | SMA_REFCLK_N | GXE_REFCLK_P | 2.5V | 2LI | GPIO_OUTCLK_N | GPIO_OUTCLK_P | GPIO_REFCLK_N | GPIO_REFCLK_P | VID | FPGA_PB0-7 | IN2_P | SYSMAX_SW0-5 | TXCO_IN | IN2_N | OUT_N | PWRMAX_SW4-5 | PWRMAX_SW0-3 | PWRMAX_PB0 | SYSMAX_PB0-5 | SYSMAX_G0-4 | OUT_1Hz | OUT_P | IN3 | FPGA_SW0-7 | SYSMAX_Y0-1 | TX | RX | MXP_RXN0 | MXP_TXN0 | LINK1000 | MXP_RXP0 | MXP_TXP0 | LINK_100 | MXP_RXN1 | MXP_TXN1 | LINK_10 | MXP_RXP1 | MXP_TXP1 | MXP_RXN2 | MXP_TXN2 | MXP_RXP2 | MXP_TXP2 | MXP_TXN3 | MXP_TXP3 | SCL | SDA | Alertn | MSEL0 | MSEL1 | MSEL2 | MSEL_EN | VREFP_ADC | VCCH_FPGA_0.9V | VREFN_ADC | ON
XSECTION_CHART: *  SURFACE - AIR 0 MIL | L1 TOP CONDUCTOR - COPPER 2 MIL | *  DIELECTRIC - M6 2.6 MIL | L2 GND02 PLANE - COPPER 0.6 MIL | *  DIELECTRIC - M6 4 MIL | L3 ART03 CONDUCTOR - COPPER 0.6 MIL | L4 GND04 PLANE - COPPER 0.6 MIL | L5 ART05 CONDUCTOR - COPPER 0.6 MIL | L6 GND06 PLANE - COPPER 0.6 MIL | L7 ART07 CONDUCTOR - COPPER 0.6 MIL | L8 GND08 PLANE - COPPER 0.6 MIL | *  DIELECTRIC - M6 3 MIL | L9 ART09 CONDUCTOR - COPPER 2.4 MIL | *  DIELECTRIC - M6 5.6 MIL | L10 GND10 PLANE - COPPER 2.4 MIL | *  DIELECTRIC - M6 2 MIL | L11 POWER11 PLANE - COPPER 2.4 MIL | L12 GND12 PLANE - COPPER 2.4 MIL | L13 POWER13 PLANE - COPPER 2.4 MIL | L14 POWER14 PLANE - COPPER 2.4 MIL | L15 GND15 PLANE - COPPER 0.6 MIL | L16 POWER16 PLANE - COPPER 0.6 MIL | L17 GND17 PLANE - COPPER 0.6 MIL | L18 ART18 CONDUCTOR - COPPER 0.6 MIL | L19 GND19 PLANE - COPPER 0.6 MIL | L20 ART20 CONDUCTOR - COPPER 0.6 MIL | L21 GND21 PLANE - COPPER 0.6 MIL | L22 BOTTOM CONDUCTOR - COPPER 2 MIL | DESIGN CROSS SECTION CHART | ___________________________ | TOTAL THICKNESS 106.8 MIL | 1-22 | B22-6-5 | B22-8-7 | BOARD NEEDS TO BE TILTED BY 7 DEGREE AS SHOWN ABOVE IN MASTER PANEL | 7  DEGREE | IMPORTANT NOTICE | BOARD
DIMENSION: ref layer | Via  Technic: | Spell Mode: | Inspectionstandard: | Compare With IPC File: | Outline Profile: | PCB Vendor Logo: | Silk Screen Colours: | Dielectric Material: | Soldermask Colours: | Surface Finished: | Finger Chamfer: | Hasl Lead Free | Yes | Green | White | Router | Hasl | Required | All via (<=12mil) must be filled. | IPCII | Angle | Board Thickness(MM): | Specified Position | IPCIII | 20 | Bridge | Immersion Tin | No | Yellow | Flash Gold | Blue | Open Windows: | +/-7% | Matte Green | Black | Immersion Gold | Immersion Silver | 30 | +/-10% | 2.7 | mm | Gjb362A-96 | V-cut | Only Date Code | None | Layers: | Gold Finger | Other | 45 | By gerber | Not Appear | Stamp Hole | 22 | Osp | L1/L22 | L3/L5/L7 | L16/L18/L20 | L5/L7 | 3.8/5.2 | 3.5/7.7 | 3.7/4.3 | 3.5/3.9 | 4.3/4.9 | 3.8/3.6 | 3.8/4.2 | 5.3/4.7 | 4.5/3 | 4.5 | 5.4 | 4.8 | 4.3 | 5.3 | 6.9 | 6.5 | 90 | 95 | 85 | 100 | 50 | 47.5 | 40 | L2/L25 | L4/L6;L6/L8; | L2/L21 | L15/L17;L17/L19;L19/L21 | L2/L4;L4/L6;L6/L8; | Purchase   Order &  Specification   Sheet | V-CUT | Note:If etch layer don't have  above impedance track pls ignore | 01-12-22 | AK | VS | AGILEX_F-SERIES_XCVR-SOC_DEV_KIT_REV_1P1_WW49P4 | M78433-001 | C | 20:  Remove soldermask for all bottom layer VIA PADs. | 30. BACKDRILL NEEDED, MAX STUB LENGTH AFTER BACKDRILL IS 8MILS, DETAILS REFER TO | 32. VENDOR NEED TO ADD TEAR DROPPING FOR PADS AND VIAS. | 33.THROUGH VIAS 1-22(DRILL SIZE LESS THAN 12MIL)MUST BE FILLED | 34. THIS MARKED AREA ON TOPSIDE NEED TO BE PLATED WITH HARD GOLD 30-50 MICRO-INCHES (MIN), | 31. WHOLE BOARD MUST BE SKEWED WITH 7 DEGREE. | SURFACE PADS IN THIS AREA TO BE FREE OF ANY PITS, SCRATCHES,PROBE MARKS, OR OTHER SURFACE | OVER NICKEL 150 - 200 MICRO-INCHES (MIN), KNOOP HARDNESS 130 -200" | ALL OTHER AREAS REQUIRE IMMERSION GOLD PLATING. | SOCKET CONTACT PAD AND STANDOFF PAD HEIGHT SHOULD BE SAME OR HIGHER THAN THE TRACES HEIGHT IN TOP | AFTER PLATING. | DEFORMITIES THAT COULD AFFECT THE APPEARANCE OR PERFORMANCE OF THE PAD. | BACKDRILL CHART. | WITH NON-CONDUCTIVE EPOXY. | ALL DIMENSIONS ARE IN MILS | PRIMARY SIDE | 11 | 35 | 31 | x4
PAGE_OUTLINE: INTEL CORPORATION. | IS RECEIVED IN CONFIDENCE AND ITS | CONTENTS MAY NOT BE DISCLOSED WITH- | THIS DRAWING CONTAINS INFORMATION | OUT THE PRIOR WRITTEN CONSENT OF | OF INTEL CORPORATION. THIS DRAWING | WHICH IS THE PROPRIETARY PROPERTY | A
PLACE_BOUND_TOP: U81 | U45 | U43 | SW4 | SW6 | SW1 | SW5
User.18: 1    2
User.19: 2    2
User.24: 140-0321330-A1 | A1
User.25: R | (c) 2017 INTEL Corporation | Blan | TANG.OWEN | 140-0321330-A1 | 07-MAR-2017 | A1 | Stratix10TX Transceiver SI Development Board | PCB ASSEMBLY | 2
User.45: SHEET | TITLE | MASTER | AM,PB,SS, | AM,PB,SM, | AM,PBASP, | INTEL | AM,PB, | SOLDER PASTE (SECONDARY) | L19_GND9   (GROUND_PLANE) | L15_GND7   (GROUND_PLANE) | SOLDER PASTE (PRIMARY) | L7_SIG3   (INTERNAL_SIGNAL) | L22_BOTTOM (SECONDAY_SIDE) | L3_SIG1   (INTERNAL_SIGNAL) | L5_SIG2   (INTERNAL_SIGNAL) | L18_SIG4   (INTERNAL_SIGNAL) | L21_GND10  (GROUND_PLANE) | L16_PWR5   (POWER_PLANE) | L2_GND1   (GROUND_PLANE) | L10_GND5   (GROUND_PLANE) | L13_GND6   (GROUND_PLANE) | SOLDER MASK (SECONDARY) | L12_PWR3   (POWER_PLANE) | L14_PWR4   (POWER_PLANE) | L11_PWR2   (POWER_PLANE) | L20_SIG5   (INTERNAL_SIGNAL) | L9_PWR1   (POWER_PLANE) | L4_GND2   (GROUND_PLANE) | L8_GND4   (GROUND_PLANE) | LEGEND (SECONDARY) | L17_GND8   (GROUND_PLANE) | L6_GND3   (GROUND_PLANE) | SOLDER MASK (PRIMARY) | L1_TOP   (PRIMARY_SIDE) | LEGEND (PRIMARY) | AGILEX_F-SERIES_XCVR-SOC_DEV_KIT_REV_1P1_WW49P4 | SCALE 1:1 | 3 | 18 | 22 | 17 | 15 | 19 | 14 | 26 | 10 | 11 | 13 | 21 | 12 | 24 | 20 | 16 | 28 | 25 | 23 | 27 | 6 | 7 | 1 | 5 | 2 | 4 | 9 | 8 | LAYER | OF | - | DOCUMENT NUMBER | M78433-001 | 01/12/22 | REV | C | NOTES: | - MNC_LAYER: MUST-NOT-CUT-LAYER | - MAX_DEPTH: DEPTH FROM START LAYER TO THE | SURFACE OF MUST-NOT-CUT-LAYER | - MFG_STUB : MANUFACTURING STUB LENGTH | FIGURE | BD_SIZE | 16.0 | MNC_LAYER | ART05 | ART07 | BACKDRILL: BOTTOM to GND06 | ALL UNITS ARE IN MILS | BACKDRILL: BOTTOM to GND08 | MAX_DEPTH | 87.8 | 78.6 | MFG_STUB | 8.0 | QTY | 88 | 40 | 84 | FINISHED_SIZE | 6.0 | 10.0 | 12.0 | 28.0 | 35.0 | 37.012 | 40.0 | 41.0 | 41.339 | 43.0 | 45.0 | 59.839 | 60.0 | 62.0 | 71.0 | 90.941 | 118.0 | 125.0 | 126.0 | 128.0 | 150.0 | 47.0 | 49.0 | 61.0 | 63.0 | 79.921 | 118.11 | TOOL_SIZE | 9.8 | DRILL CHART: TOP to BOTTOM | TOLERANCE_DRILL | +1.0/-6.0 | +3.0/-8.0 | +2.0/-3.0 | +2.0/-10.0 | +3.0/-12.0 | +3.0/-3.0 | +1.969/-1.969 | +2.0/-2.0 | +30.0/-3.0 | PLATED | NON-PLATED | 48 | 6430 | 112 | 2721 | 691 | 1396 | 224 | 68 | REFLOW PROCESS DIRECTION | WAVE PROCESS DIRECTION
